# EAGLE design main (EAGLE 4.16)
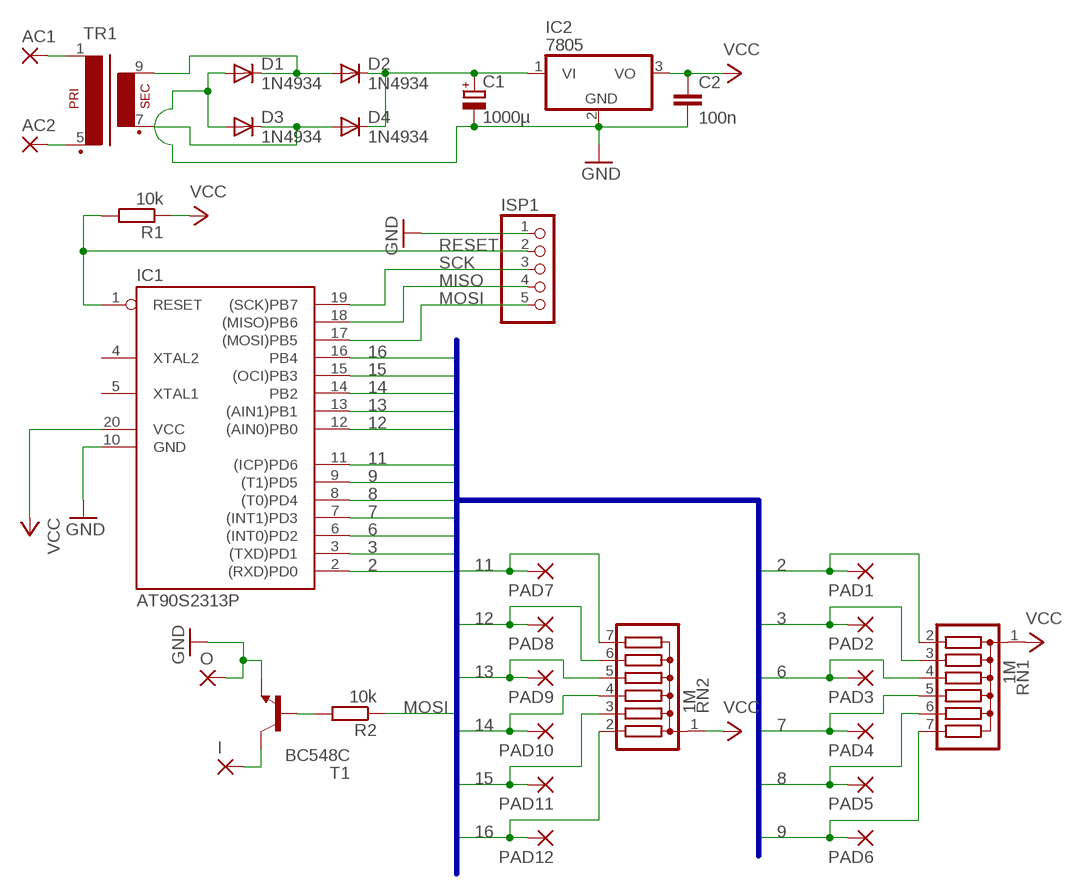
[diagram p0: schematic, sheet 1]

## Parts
AC1  1,6/0,8  [1,6/0,8]
AC2  1,6/0,8  [1,6/0,8]
C1  1000µ  CPOL-EUE5-10.5  [E5-10,5]
C2  100n  C-EU025-025X050  [C025-025X050]
D1  1N4934  1N4446  [DO35-10]
D2  1N4934  1N4446  [DO35-10]
D3  1N4934  1N4446  [DO35-10]
D4  1N4934  1N4446  [DO35-10]
I  1,6/0,8  [1,6/0,8]
IC1  AT90S2313P  [DIL20]
IC2  7805  [TO220V]
ISP1  PINHD-1X5  [1X05]
O  1,6/0,8  [1,6/0,8]
PAD1  1,6/0,8  [1,6/0,8]
PAD2  1,6/0,8  [1,6/0,8]
PAD3  1,6/0,8  [1,6/0,8]
PAD4  1,6/0,8  [1,6/0,8]
PAD5  1,6/0,8  [1,6/0,8]
PAD6  1,6/0,8  [1,6/0,8]
PAD7  1,6/0,8  [1,6/0,8]
PAD8  1,6/0,8  [1,6/0,8]
PAD9  1,6/0,8  [1,6/0,8]
PAD10  1,6/0,8  [1,6/0,8]
PAD11  1,6/0,8  [1,6/0,8]
PAD12  1,6/0,8  [1,6/0,8]
R1  10k  R-EU_0207/2V  [0207/2V]
R2  10k  R-EU_0207/2V  [0207/2V]
RN1  1M  G06R  [SIL7]
RN2  1M  G06R  [SIL7]
T1  BC548C  BC548C-NPN-TO92-EBC  [TO92-EBC]
TR1  EI30-1  [EI30-1]

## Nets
2: IC1.2((RXD)PD0) PAD1.1(P) RN1.2
3: IC1.3((TXD)PD1) PAD2.1(P) RN1.3
6: IC1.6((INT0)PD2) PAD3.1(P) RN1.4
7: IC1.7((INT1)PD3) PAD4.1(P) RN1.5
8: IC1.8((T0)PD4) PAD5.1(P) RN1.6
9: IC1.9((T1)PD5) PAD6.1(P) RN1.7
11: IC1.11((ICP)PD6) PAD7.1(P) RN2.7
12: IC1.12((AIN0)PB0) PAD8.1(P) RN2.6
13: IC1.13((AIN1)PB1) PAD9.1(P) RN2.5
14: IC1.14(PB2) PAD10.1(P) RN2.4
15: IC1.15((OCI)PB3) PAD11.1(P) RN2.3
16: IC1.16(PB4) PAD12.1(P) RN2.2
GND: C1.- C2.2 D1.A D3.A IC1.10(GND) IC2.2(GND) ISP1.1 O.1(P) T1.E
MISO: IC1.18((MISO)PB6) ISP1.4
MOSI: IC1.17((MOSI)PB5) ISP1.5 R2.1
N$1: I.1(P) T1.C
N$3: AC1.1(P) TR1.1
N$4: AC2.1(P) TR1.5(P2)
N$5: C1.+ D2.C D4.C IC2.1(VI)
N$6: D1.C D2.A TR1.9(S4)
N$7: D3.C D4.A TR1.7(S3)
N$8: R2.2 T1.B
RESET: IC1.1(RESET) ISP1.2 R1.2
SCK: IC1.19((SCK)PB7) ISP1.3
VCC: C2.1 IC1.20(VCC) IC2.3(VO) R1.1 RN1.1 RN2.1
Unconnected: IC1.4(XTAL2) IC1.5(XTAL1)

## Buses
B$1

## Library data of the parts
AC1 AC2 I O PAD1-PAD12 = wirepad:1,6/0,8: THROUGH-HOLE PAD
C1 = rcl:CPOL-EU: POLARIZED CAPACITOR, European symbol
C2 = rcl:C-EU: CAPACITOR, European symbol
D1-D4 = diode:1N4446: DIODE
IC1 = atmel:AT90S2313: MICROCONTROLLER 2 Kbytes FLASH 128 bytes SRAM 128 bytes EEPROM UART
IC2 = linear:78*: Positive VOLTAGE REGULATOR Source: http://cache.national.com/ds/LM/LM78L05.pdf http://www.fairchildsemi.com/ds/LM/LM7805.pdf
ISP1 = pinhead:PINHD-1X5: PIN HEADER
R1 R2 = rcl:R-EU_: RESISTOR, European symbol
RN1 RN2 = resistor-sil:G06R: SIL RESISTOR
T1 = transistor:*-NPN-: NPN Transistror
TR1 = trafo:EI30-1: TRANSFORMER 1 primary winding, 1 secondary winding ERA

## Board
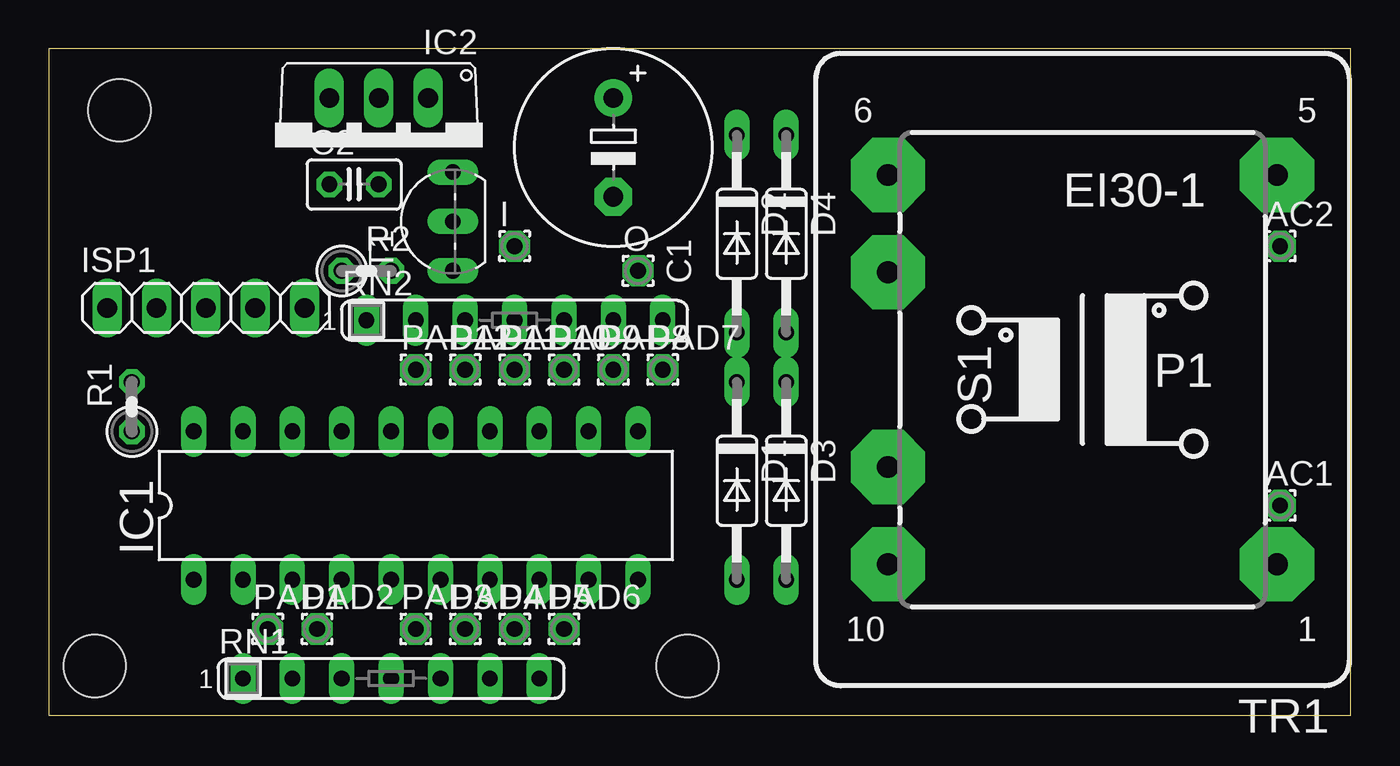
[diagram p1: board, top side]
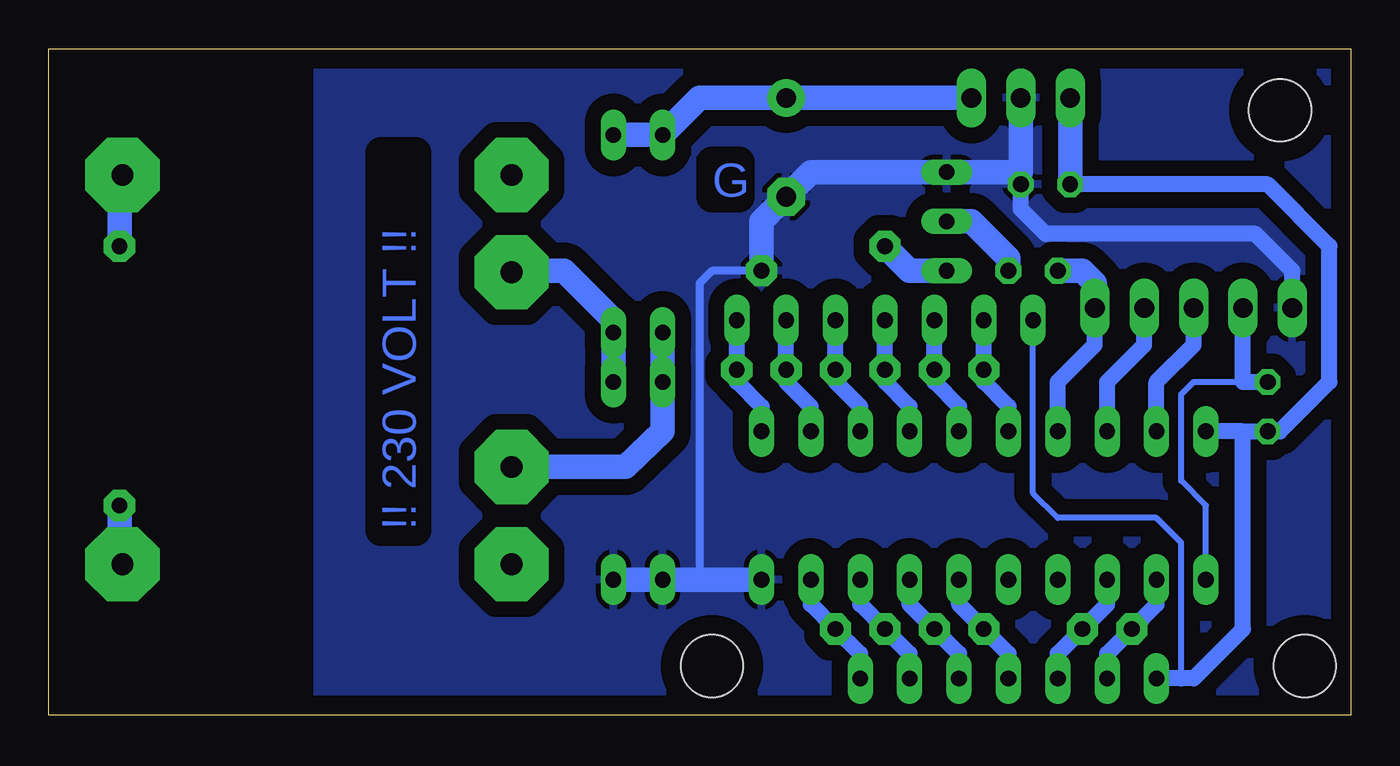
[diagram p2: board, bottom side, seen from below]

Size 66.98 x 34.28 mm. Coordinates in mm from the lower left corner, seen from the top.
Outline: 0,0 66.98,0 66.98,34.28 0,34.28 0,0
Copper layers (1*16): Top 0.035mm / dielectric 1.5mm / Bottom 0.035mm
Design rules "default": minimum track width 10mil, minimum drill 24mil, track to track 8mil, track to pad 8mil, pad to pad 8mil, via to via 8mil, smd to smd 8mil, copper to edge 40mil, drill to drill 8mil, minimum pad ring 10mil, minimum via ring 8mil, stop-mask expansion 4mil, vias tented up to drill 0mil, thermal gap 10mil
Holes 3.2 mm at 3.65,31.11 32.85,2.54 2.37,2.54

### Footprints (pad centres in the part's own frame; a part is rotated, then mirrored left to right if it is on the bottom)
1,6/0,8 = drill 0.813 pad 1.6 octagon: 1 0,0
E5-10,5 = drill 1.016 pad 1.93 round: + -2.54,0 | drill 1.016 pad 1.93 octagon: - 2.54,0
C025-025X050 = drill 0.813 octagon: 1 -1.27,0; 2 1.27,0
DO35-10 = drill 0.813 long: A 5.08,0; C -5.08,0
DIL20 = drill 0.813 long: 1 -11.43,-3.81; 2 -8.89,-3.81; 3 -6.35,-3.81; 4 -3.81,-3.81; 5 -1.27,-3.81; 6 1.27,-3.81; 7 3.81,-3.81; 8 6.35,-3.81; 9 8.89,-3.81; 10 11.43,-3.81; 11 11.43,3.81; 12 8.89,3.81; 13 6.35,3.81; 14 3.81,3.81; 15 1.27,3.81; 16 -1.27,3.81; 17 -3.81,3.81; 18 -6.35,3.81; 19 -8.89,3.81; 20 -11.43,3.81
TO220V = drill 1.016 long: 1 -2.54,-2.54; 2 0,-2.54; 3 2.54,-2.54
1X05 = drill 1.016 long: 1 -5.08,0; 2 -2.54,0; 3 0,0; 4 2.54,0; 5 5.08,0
0207/2V = drill 0.813 octagon: 1 -1.27,0; 2 1.27,0
SIL7 = drill 0.813 long: 1 -7.62,0; 2 -5.08,0; 3 -2.54,0; 4 0,0; 5 2.54,0; 6 5.08,0; 7 7.62,0
TO92-EBC = drill 0.813 long: B 0,-1.27; C -2.54,-1.27; E 2.54,-1.27
EI30-1 = drill 1.118 pad 3.81 octagon: 1 -10.008,10.008; 5 -10.008,-10.008; 6 10.008,-10.008; 7 10.008,-5.004; 9 10.008,5.004; 10 10.008,10.008

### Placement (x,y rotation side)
AC1  63.34,10.79 0 top
AC2  63.34,24.12 0 top
C1  29.05,29.21 270 top
C2  15.71,27.3 0 top
D1  35.39,12.06 270 top
D2  35.39,24.76 270 top
D3  37.93,12.06 270 top
D4  37.93,24.76 270 top
I  23.96,24.12 0 top
IC1  18.88,10.79 0 top
IC2  16.98,29.21 180 top
ISP1  8.09,20.95 0 top
O  30.31,22.86 0 top
PAD1  11.27,4.44 0 top
PAD2  13.81,4.44 0 top
PAD3  18.88,4.44 0 top
PAD4  21.42,4.44 0 top
PAD5  23.96,4.44 0 top
PAD6  26.5,4.44 0 top
PAD7  31.59,17.78 0 top
PAD8  29.05,17.78 0 top
PAD9  26.5,17.78 0 top
PAD10  23.96,17.78 0 top
PAD11  21.42,17.78 0 top
PAD12  18.88,17.78 0 top
R1  4.28,15.87 90 top
R2  16.34,22.86 0 top
RN1  17.61,1.9 0 top
RN2  23.96,20.32 0 top
T1  19.52,25.4 90 top
TR1  53.17,17.78 180 top

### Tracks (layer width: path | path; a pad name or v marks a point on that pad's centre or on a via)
2
  Bottom 0.813: IC1.2 10,5.71 PAD1.1 12.54,3.17 RN1.2
3
  Bottom 0.813: IC1.3 12.54,5.71 PAD2.1 15.08,3.17 RN1.3
6
  Bottom 0.813: IC1.6 20.15,5.71 PAD3.1 17.61,3.17 RN1.4
7
  Bottom 0.813: IC1.7 22.7,5.71 PAD4.1 20.15,3.17 RN1.5
8
  Bottom 0.813: IC1.8 25.23,5.71 PAD5.1 22.7,3.17 RN1.6
9
  Bottom 0.813: IC1.9 27.77,5.71 PAD6.1 25.23,3.17 RN1.7
11
  Bottom 0.813: IC1.11 30.31,15.87 31.59,17.14 PAD7.1 RN2.7
12
  Bottom 0.813: IC1.12 27.77,15.87 29.05,17.14 PAD8.1 RN2.6
13
  Bottom 0.813: IC1.13 25.23,15.87 26.5,17.14 PAD9.1 RN2.5
14
  Bottom 0.813: IC1.14 22.7,15.87 23.96,17.14 PAD10.1 RN2.4
15
  Bottom 0.813: IC1.15 20.15,15.87 21.42,17.14 PAD11.1 RN2.3
16
  Bottom 0.813: IC1.16 17.61,15.87 18.88,17.14 PAD12.1 RN2.2
GND
  Bottom 0.406: 33.49,6.98 33.49,22.22 32.85,22.86 O.1 | C2.2 16.98,27.94
  Bottom 0.813: ISP1.1 3.01,22.86 4.92,24.76 15.71,24.76 16.98,26.03 C2.2
  Bottom 1.27: D3.A D1.A 33.49,6.98 IC1.10 | IC2.2 16.98,27.94 T1.E 27.77,27.94 C1.- 30.31,25.4 O.1
  pour Bottom (isolate 0.813): -0.17,34.29 53.17,34.29 53.17,-0.64 -0.17,-0.64
MISO
  Bottom 0.813: IC1.18 12.54,17.14 10.63,19.05 ISP1.4
MOSI
  Bottom 0.813: IC1.17 15.08,17.14 13.17,19.05 ISP1.5
  Bottom 1.27: R2.1 13.81,22.86 13.17,22.22 ISP1.5
N$1
  Bottom 1.27: T1.C 22.7,22.86 I.1
N$3
  Bottom 1.27: TR1.1 63.34,8.4 AC1.1
N$4
  Bottom 1.27: TR1.5 63.34,27.78 AC2.1
N$5
  Bottom 1.27: D4.C D2.C 33.49,31.75 | 33.49,31.75 C1.+ | IC2.1 33.49,31.75
N$6
  Bottom 1.27: TR1.9 37.3,12.77 35.39,14.6 D1.C D2.A
N$7
  Bottom 0.406: 43.02,22.86 43.02,22.78
  Bottom 1.27: D3.C D4.A 37.93,20.32 40.48,22.86 43.02,22.86 | 43.02,22.78 TR1.7
N$8
  Bottom 1.27: T1.B 19.52,25.4 17.61,23.49 R2.2
RESET
  Bottom 0.305: IC1.1 7.46,10.79 8.72,12.06 8.72,16.51 8.09,17.14 5.55,17.14
  Bottom 0.813: ISP1.2 5.55,17.14 R1.2
SCK
  Bottom 0.813: IC1.19 10,17.14 8.09,19.05 ISP1.3
VCC
  Bottom 0.305: RN2.1 16.34,11.43 15.08,10.15 10,10.15 8.72,8.88 8.72,1.9
  Bottom 0.813: 5.55,14.6 IC1.20 | RN1.1 8.72,1.9 8.09,1.9 5.55,4.44 5.55,14.6 | 5.55,14.6 R1.1 3.65,14.6 1.1,17.14 1.1,24.12 4.28,27.3 C2.1
  Bottom 1.27: C2.1 IC2.3

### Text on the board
Bottom: G | !! 230 VOLT !!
